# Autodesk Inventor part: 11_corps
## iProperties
Shininess: 20.0
Length Units: 11270
Angle Units: 11279
Time Units: 11290
Mass Units: 11283
Length Display Precision: 3
Angle Display Precision: 2
Created: 2000-10
Part Number: 11_corps
Material: Par défaut
Document SubType Name: Modélisation
Density: 0.0
Volumn: 0.0
Area: 0.0
PropertySet Name: Model Information
Control State: 0
Master: False
Checked Out: False
Author: Laurent GAUTHERON
